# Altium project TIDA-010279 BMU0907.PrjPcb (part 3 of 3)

## Sheet TIDA-010279 BMU_Hardware.SchDoc
size 431 x 279 mm; Date: Not shown in title block; ApprovedBy: Not shown in title block; CheckedBy: Not shown in title block; Author: Not shown in title block; CompanyName: Not shown in title block; Engineer: Not shown in title block; Organization: Not shown in title block; Address1: Not shown in title block; Address2: Not shown in title block; Address3: Not shown in title block; Address4: Not shown in title block; DocumentNumber: 3; Revision: Use project parameter SCH_Rev; SheetNumber: 3; SheetTotal: 4; PageSetup: Record=PageOptions¦CenterHorizontal=True¦CenterVertical=True¦PrintScale=1.00¦XCorrection=1.00¦YCorrection=1.00¦PrintKind=0¦BorderSize=5000000¦LeftOffset=0¦BottomOffset=0¦Orientation=2¦PaperLength=1000¦PaperWidth=1000¦Scale=100¦PaperSource=15¦PrintQuality=600¦MediaType=1¦DitherType=10¦PaperKind=Letter¦PrintScaleMode=1
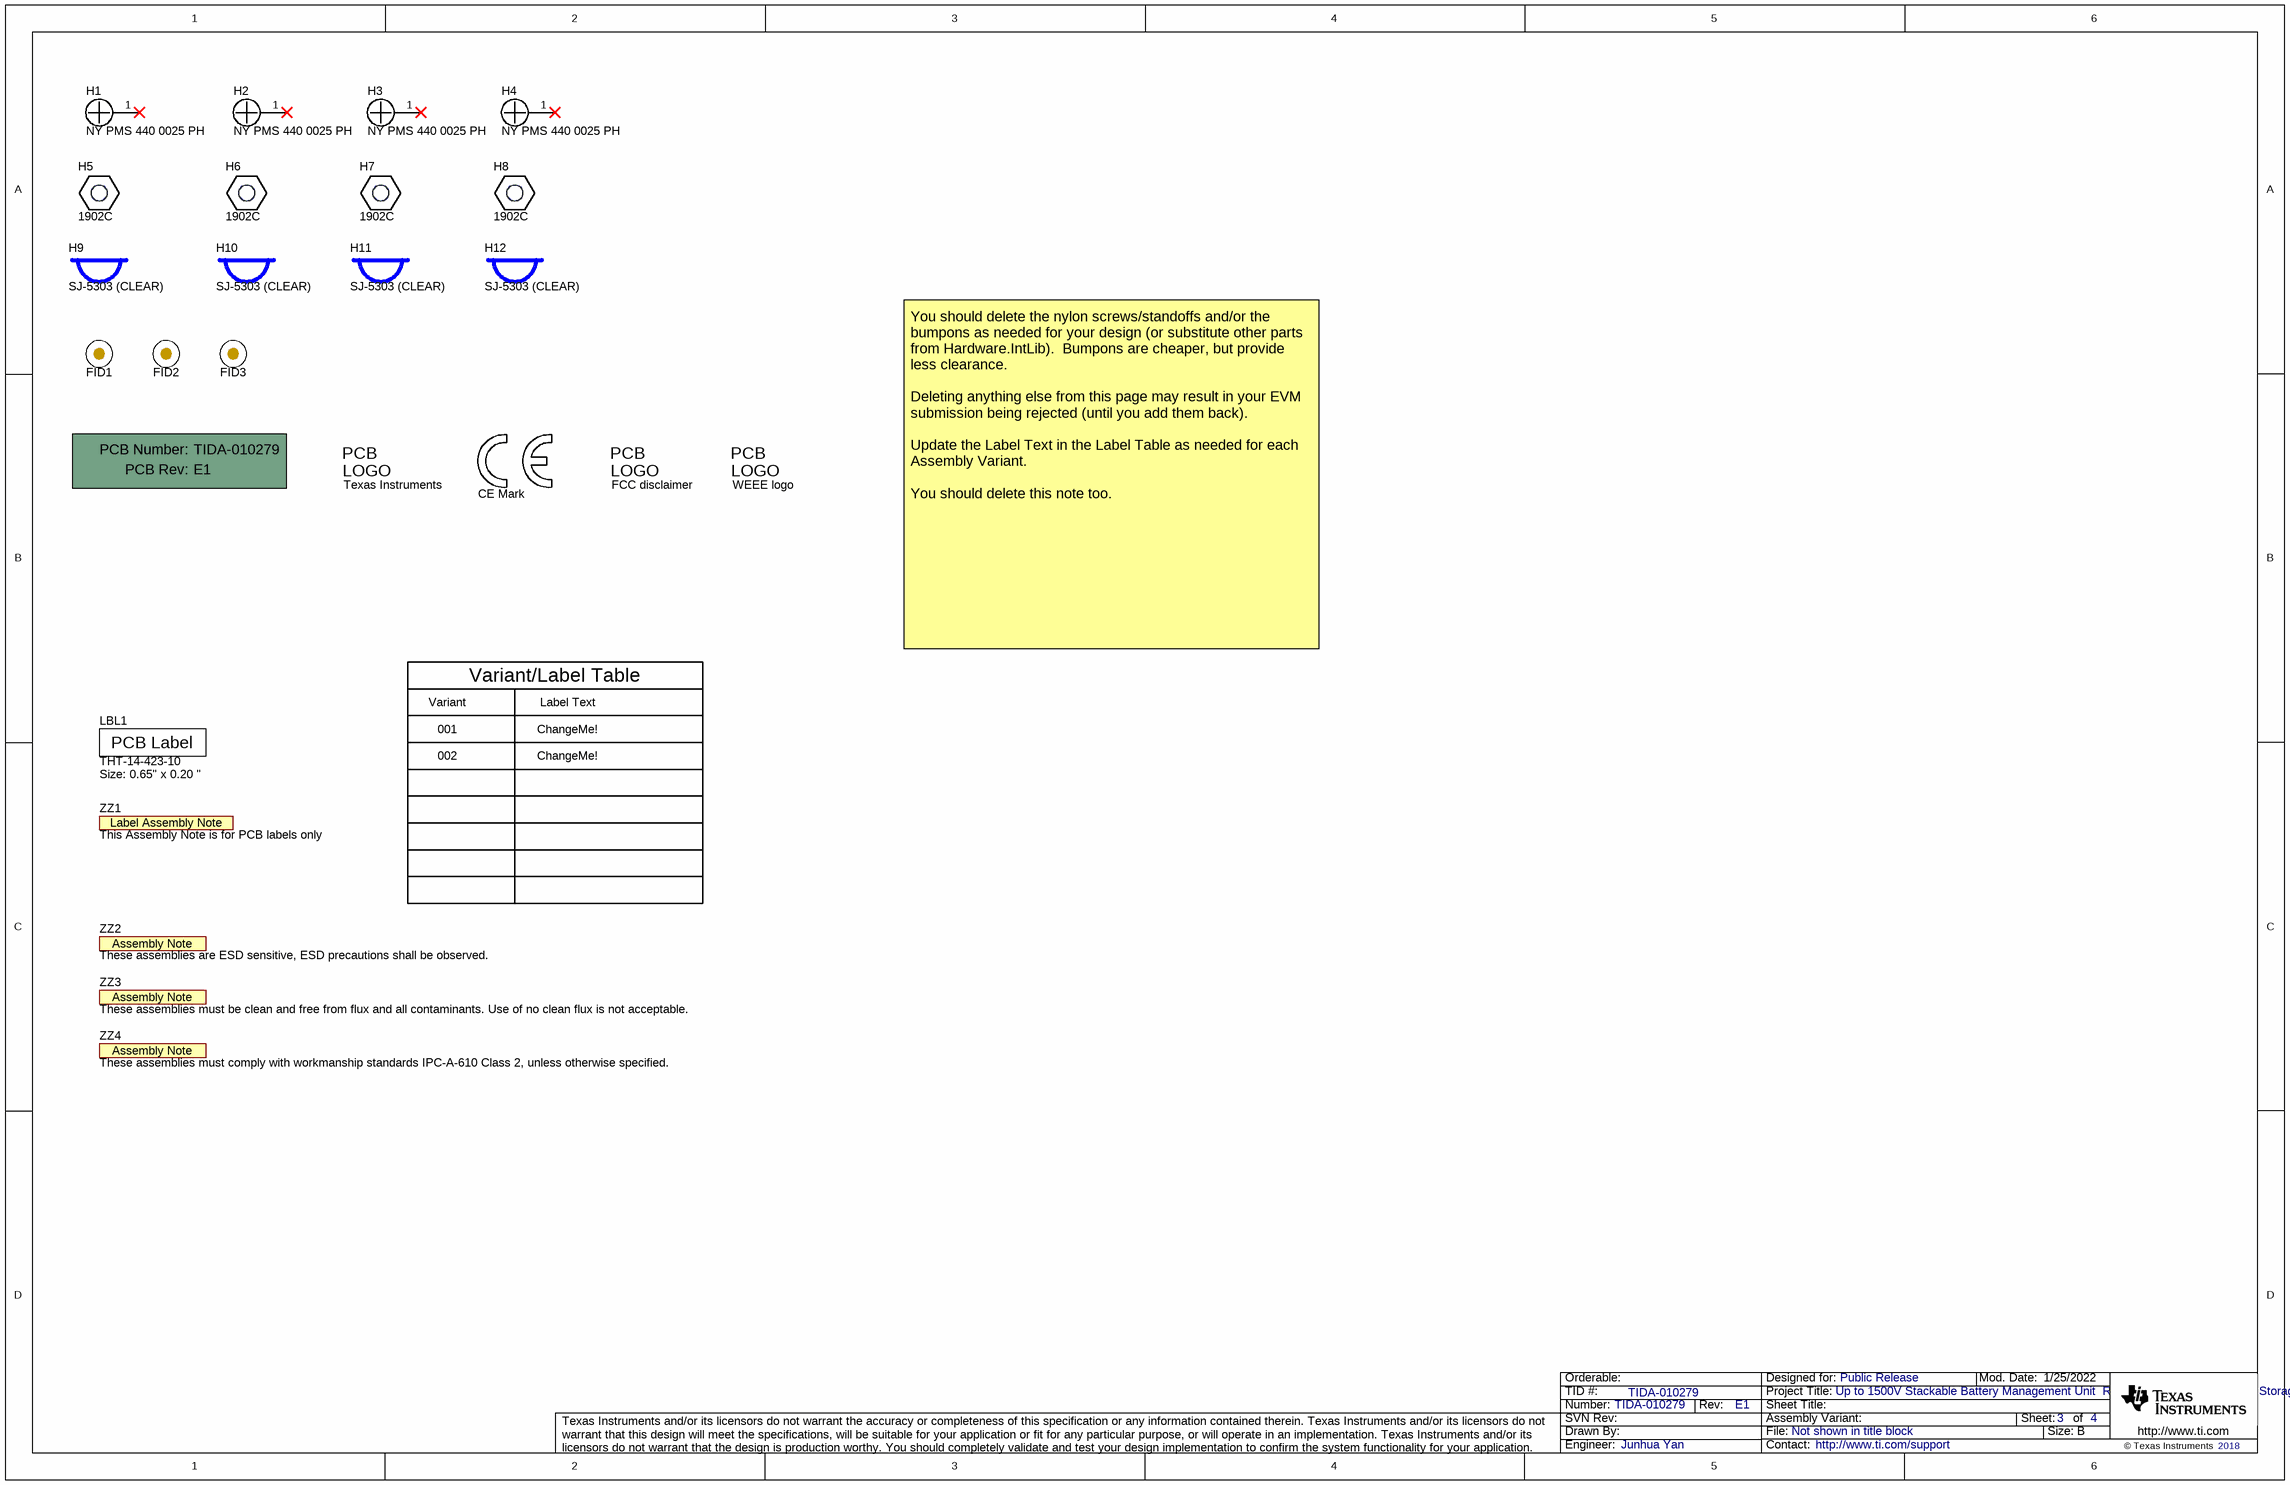
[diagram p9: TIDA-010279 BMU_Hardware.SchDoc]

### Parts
!PCB  Printed Circuit Board  (value not drawn)  (mechanical)
FID1  Fiducial  [Fiducial10-20]  (value not drawn)
FID2  Fiducial  [Fiducial10-20]  (value not drawn)
FID3  Fiducial  [Fiducial10-20]  (value not drawn)
H1  NY PMS 440 0025 PH  [NY PMS 440 0025 PH]
H2  NY PMS 440 0025 PH  [NY PMS 440 0025 PH]
H3  NY PMS 440 0025 PH  [NY PMS 440 0025 PH]
H4  NY PMS 440 0025 PH  [NY PMS 440 0025 PH]
H5  1902C  [Keystone_1902C]
H6  1902C  [Keystone_1902C]
H7  1902C  [Keystone_1902C]
H8  1902C  [Keystone_1902C]
H9  SJ-5303 (CLEAR)  [Bumpon_SJ5003Transparent]
H10  SJ-5303 (CLEAR)  [Bumpon_SJ5003Transparent]
H11  SJ-5303 (CLEAR)  [Bumpon_SJ5003Transparent]
H12  SJ-5303 (CLEAR)  [Bumpon_SJ5003Transparent]
LBL1  THT-14-423-10  Note: Size: 0.65" x 0.20 "  [Label_650x200]
Logo1  Texas Instruments  [TI_Stacked_Overlay_Small]  (no BOM)
Logo2  CE Mark  [CE_Mark_5mm]  (no BOM)
Logo3  FCC disclaimer  [FCC_disclaimer]  (no BOM)
Logo4  WEEE logo  [WEEE_Minimum]  (no BOM)
ZZ1  This Assembly Note is for PCB labels only  [AssemblyNoteLabel]  (no BOM)
ZZ2  These assemblies are ESD sensitive, ESD precautions shall be observed.  [AssemblyNote]  (no BOM)
ZZ3  These assemblies must be clean and free from flux and all contaminants. Use of no clean flux is not acceptable.  [AssemblyNote]  (no BOM)
ZZ4  These assemblies must comply with workmanship standards IPC-A-610 Class 2, unless otherwise specified.  [AssemblyNote]  (no BOM)

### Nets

Not connected (* = marked no-connect by the designer): H1 1*; H2 1*; H3 1*; H4 1*

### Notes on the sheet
- Variant
- Variant/Label Table
- Label Text
- You should delete the nylon screws/standoffs and/or the bumpons as needed for your design (or substitute other parts from Hardware.IntLib).  Bumpons are cheaper, but provide less clearance.
  Deleting anything else from this page may result in your EVM submission being rejected (until you add them back).
  Update the Label Text in the Label Table as needed for each Assembly Variant.
  You should delete this note too.
- 001
- 002
- ChangeMe!

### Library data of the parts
!PCB = CMP-0003618-2: Manufacturer: Any; PartNumber: TIDA-010279
FID1-FID3 = CMP-0077181-1: Fiducial mark.  There is nothing to buy or mount.
H1-H4 = CMP-0003617-1: Machine Screw, Round, #4-40 x 1/4, Nylon, Philips panhead; Manufacturer: B&F Fastener Supply; CompType: Hardware
H5-H8 = CMP-0003610-1: Standoff, Hex, 0.5"L #4-40 Nylon; Manufacturer: Keystone; CompType: Hardware
H9-H12 = CMP-0003620-1: Bumpon, Hemisphere, 0.44 X 0.20, Clear; Manufacturer: 3M
LBL1 = CMP-0003625-1: Thermal Transfer Printable Labels, 0.650" W x 0.200" H - 10,000 per roll; Manufacturer: Brady; CompType: Label
Logo1 = CMP-0074838-1: Texas Instrument Corporate Signature; SymbolCreator: a0412235; Lib Reference: TI_Logo; Library Reference: Logo
Logo2 = CMP-0074844-2: Manufacturer: Texas Instruments; SymbolCreator: a0412235; AEC Category: Q200; CompType: IC
Logo3 = CMP-0074847-1: FCC_disclaimer; Library Reference: Logo
Logo4 = CMP-0074769-4: Manufacturer: Texas Instruments; CompType: IC; AEC Category: Q200
ZZ1 = CMP-0003616-3
ZZ2 = CMP-0077236-1
ZZ3 = CMP-0077237-1
ZZ4 = CMP-0077238-1

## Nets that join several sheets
GND: TIDA-010279 BMU_Schematic_Block (9 pins), A1 (97 pins), A2 (97 pins), A3 (97 pins), A4 (97 pins)
GND_Stage2: TIDA-010279 BMU_Schematic_Block (R211.2), TIDA-010279 BMU_CAN MCU (10 pins)
PGND: TIDA-010279 BMU_Schematic_Block (J5.1 S1.1 S1.2), TIDA-010279 BMU_CAN MCU (69 pins)
AFE_FLT: TIDA-010279 BMU_Schematic_Block (R210.2), TIDA-010279 BMU_CAN MCU (U50.3)
AFE_RX: TIDA-010279 BMU_Schematic_Block (R208.2), TIDA-010279 BMU_CAN MCU (Q7.3)
AFE_TX: TIDA-010279 BMU_Schematic_Block (R209.2), TIDA-010279 BMU_CAN MCU (U50.4)
BMU_WAKEIN_C: TIDA-010279 BMU_Schematic_Block (J5.6 S1.4), TIDA-010279 BMU_CAN MCU (D15.2)
BMU_WAKEOUT_C: TIDA-010279 BMU_Schematic_Block (J5.2), TIDA-010279 BMU_CAN MCU (R230.2 R231.2 R232.2)
CAN0_CANH: TIDA-010279 BMU_Schematic_Block (J5.3 J5.8), TIDA-010279 BMU_CAN MCU (6 pins)
CAN0_CANL: TIDA-010279 BMU_Schematic_Block (J5.4 J5.7), TIDA-010279 BMU_CAN MCU (6 pins)
COMMH_N_OPT: TIDA-010279 BMU_Schematic_Block (C163.1 T2.3), A1 (J4_A1.2 R195_A1.2)
COMMH_N_OPT: TIDA-010279 BMU_Schematic_Block (C164.1 T3.3), A2 (J4_A2.2 R195_A2.2)
COMMH_N_OPT: TIDA-010279 BMU_Schematic_Block (C165.1 T4.3), A3 (J4_A3.2 R195_A3.2)
COMMH_N_OPT: TIDA-010279 BMU_Schematic_Block (T5.6), A4 (J4_A4.2 R195_A4.2)
COMMH_P_OPT: TIDA-010279 BMU_Schematic_Block (C153.2 T2.1), A1 (J4_A1.1 R182_A1.2)
COMMH_P_OPT: TIDA-010279 BMU_Schematic_Block (C154.2 T3.1), A2 (J4_A2.1 R182_A2.2)
COMMH_P_OPT: TIDA-010279 BMU_Schematic_Block (C155.2 T4.1), A3 (J4_A3.1 R182_A3.2)
COMMH_P_OPT: TIDA-010279 BMU_Schematic_Block (T5.4), A4 (J4_A4.1 R182_A4.2)
COMML_N_OPT: TIDA-010279 BMU_Schematic_Block (C163.2 T2.4), A2 (J3_A2.2 R190_A2.1)
COMML_N_OPT: TIDA-010279 BMU_Schematic_Block (C164.2 T3.4), A3 (J3_A3.2 R190_A3.1)
COMML_N_OPT: TIDA-010279 BMU_Schematic_Block (C165.2 T4.4), A4 (J3_A4.2 R190_A4.1)
COMML_N_OPT: TIDA-010279 BMU_Schematic_Block (T1.4), A1 (J3_A1.2 R190_A1.1)
COMML_P_OPT: TIDA-010279 BMU_Schematic_Block (C153.1 T2.6), A2 (J3_A2.1 R177_A2.1)
COMML_P_OPT: TIDA-010279 BMU_Schematic_Block (C154.1 T3.6), A3 (J3_A3.1 R177_A3.1)
COMML_P_OPT: TIDA-010279 BMU_Schematic_Block (C155.1 T4.6), A4 (J3_A4.1 R177_A4.1)
COMML_P_OPT: TIDA-010279 BMU_Schematic_Block (T1.6), A1 (J3_A1.1 R177_A1.1)
LV24V: TIDA-010279 BMU_Schematic_Block (J5.5 S1.3), TIDA-010279 BMU_CAN MCU (C179.1 C180.1 D13.2 L2.1)
NFAULT/GPIO2: TIDA-010279 BMU_Schematic_Block (R210.1), A1 (6 pins)
RX/GPIO0: TIDA-010279 BMU_Schematic_Block (R208.1), A1 (R257_A1.1 U1_A1.51)
TX/GPIO1: TIDA-010279 BMU_Schematic_Block (R209.1), A1 (C110_A1.1 R145_A1.1 U1_A1.52)

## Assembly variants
BQ78706*4: not fitted C37_A1 C37_A2 C37_A4 C110_A1 C157 C158 C159 C160 C161 C162 FID1 FID2 FID3 H9 H10 H11 H12 R145_A1 R196_AFE1 R196_AFE2 R196_AFE3 R196_AFE4 R199_AFE1 R199_AFE2 R199_AFE3 R199_AFE4 R215_A2 R215_A3 R215_A4 R215_AFE1 R257_AFE1 T2 T3 T4
BQ79718*3: all parts fitted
